// Mitsubishi GX Works2 project: ModbusTCP案例   PLC: L02

PROGRAM MAIN
0     END
END_PROGRAM

PROGRAM MB_TCP
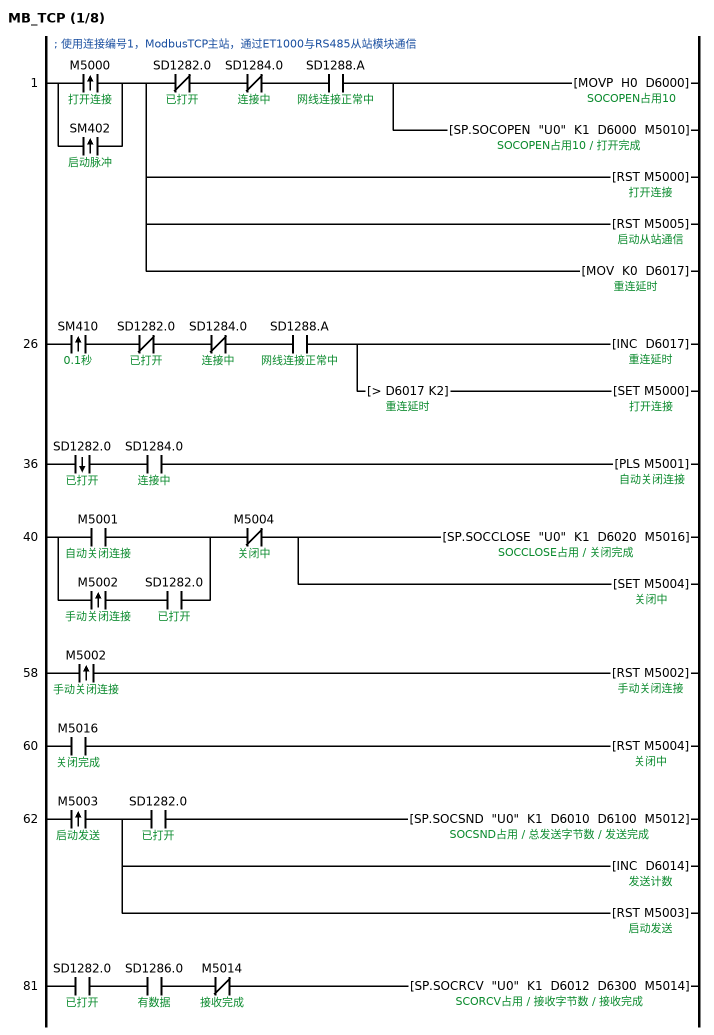
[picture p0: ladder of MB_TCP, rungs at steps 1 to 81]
; 使用连接编号1，ModbusTCP主站，通过ET1000与RS485从站模块通信
1     LDP     M5000  ; 打开连接
      ORP     SM402  ; 启动脉冲
      MPS
      ANI     SD1282.0  ; 已打开
      ANI     SD1284.0  ; 连接中
      AND     SD1288.A  ; 网线连接正常中
      MOVP    H0 D6000  ; SOCOPEN占用10
      SP.SOCOPEN "U0" K1 D6000 M5010  ; 打开完成
      MPP
      RST     M5000  ; 打开连接
      RST     M5005  ; 启动从站通信
      MOV     K0 D6017  ; 重连延时
26    LDP     SM410  ; 0.1秒
      ANI     SD1282.0  ; 已打开
      ANI     SD1284.0  ; 连接中
      AND     SD1288.A  ; 网线连接正常中
      INC     D6017
      AND>    D6017 K2  ; 重连延时
      SET     M5000  ; 打开连接
36    LDF     SD1282.0  ; 已打开
      AND     SD1284.0  ; 连接中
      PLS     M5001  ; 自动关闭连接
40    LD      M5001  ; 自动关闭连接
      LDP     M5002  ; 手动关闭连接
      AND     SD1282.0  ; 已打开
      ORB
      ANI     M5004  ; 关闭中
      SP.SOCCLOSE "U0" K1 D6020 M5016  ; SOCCLOSE占用 / 关闭完成
      SET     M5004  ; 关闭中
58    LDP     M5002  ; 手动关闭连接
      RST     M5002  ; 手动关闭连接
60    LD      M5016  ; 关闭完成
      RST     M5004  ; 关闭中
62    LDP     M5003  ; 启动发送
      MPS
      AND     SD1282.0  ; 已打开
      SP.SOCSND "U0" K1 D6010 D6100 M5012  ; SOCSND占用 / 总发送字节数 / 发送完成
      MPP
      INC     D6014  ; 发送计数
      RST     M5003  ; 启动发送
81    LD      SD1282.0  ; 已打开
      AND     SD1286.0  ; 有数据
      ANI     M5014  ; 接收完成
      SP.SOCRCV "U0" K1 D6012 D6300 M5014  ; SCORCV占用 / 接收字节数
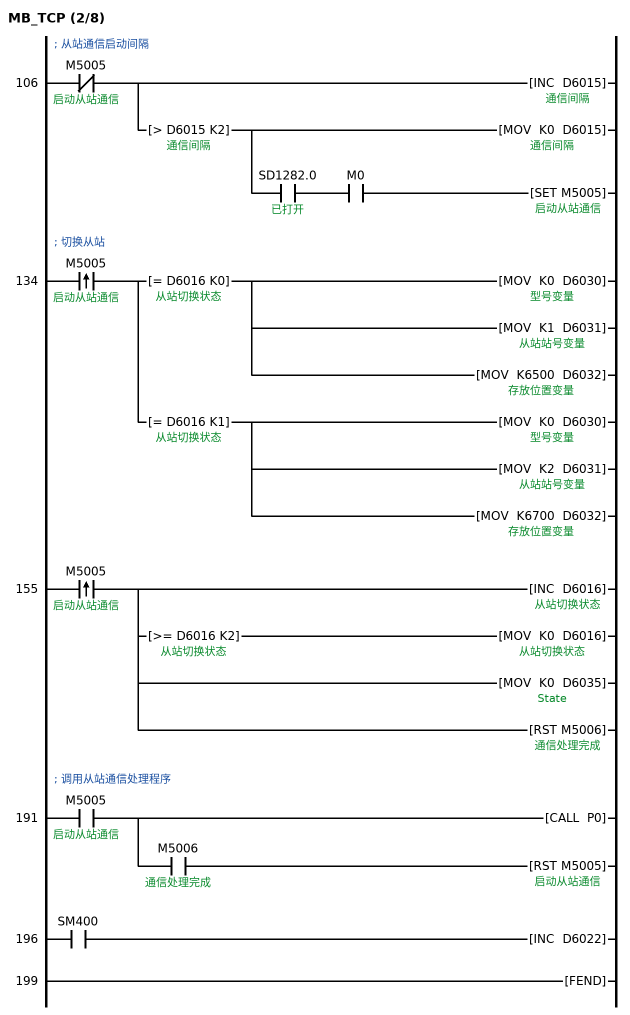
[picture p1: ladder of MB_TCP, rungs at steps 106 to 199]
; 从站通信启动间隔
106   LDI     M5005  ; 启动从站通信
      INC     D6015  ; 通信间隔
      AND>    D6015 K2  ; 通信间隔
      MOV     K0 D6015
      AND     SD1282.0  ; 已打开
      AND     M0
      SET     M5005  ; 启动从站通信
; 切换从站
134   LDP     M5005  ; 启动从站通信
      MPS
      AND=    D6016 K0  ; 从站切换状态
      MOV     K0 D6030  ; 型号变量
      MOV     K1 D6031  ; 从站站号变量
      MOV     K6500 D6032  ; 存放位置变量
      MPP
      AND=    D6016 K1  ; 从站切换状态
      MOV     K0 D6030
      MOV     K2 D6031
      MOV     K6700 D6032
155   LDP     M5005  ; 启动从站通信
      INC     D6016
      MPS
      AND>=   D6016 K2  ; 从站切换状态
      MOV     K0 D6016
      MPP
      MOV     K0 D6035  ; State
      RST     M5006  ; 通信处理完成
; 调用从站通信处理程序
191   LD      M5005  ; 启动从站通信
      CALL    P0
      AND     M5006  ; 通信处理完成
      RST     M5005  ; 启动从站通信
196   LD      SM400
      INC     D6022
199   FEND
; 对不同从站通信处理载程序
      P0
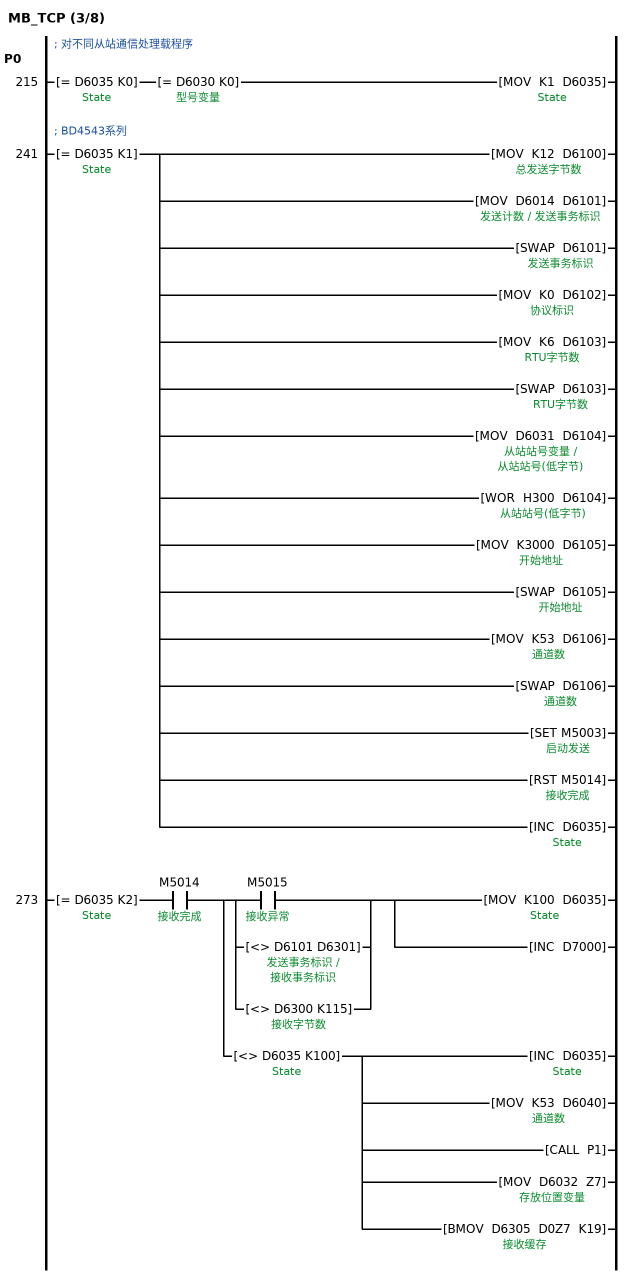
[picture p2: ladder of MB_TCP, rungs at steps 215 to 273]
215   LD=     D6035 K0  ; State
      AND=    D6030 K0  ; 型号变量
      MOV     K1 D6035
; BD4543系列
241   LD=     D6035 K1  ; State
      MOV     K12 D6100
      MOV     D6014 D6101  ; 发送事务标识
      SWAP    D6101
      MOV     K0 D6102  ; 协议标识
      MOV     K6 D6103  ; RTU字节数
      SWAP    D6103
      MOV     D6031 D6104  ; 从站站号(低字节)
      WOR     H300 D6104
      MOV     K3000 D6105  ; 开始地址
      SWAP    D6105
      MOV     K53 D6106  ; 通道数
      SWAP    D6106
      SET     M5003  ; 启动发送
      RST     M5014  ; 接收完成
      INC     D6035
273   LD=     D6035 K2  ; State
      AND     M5014  ; 接收完成
      MPS
      LD      M5015  ; 接收异常
      OR<>    D6101 D6301  ; 发送事务标识 / 接收事务标识
      OR<>    D6300 K115  ; 接收字节数
      ANB
      MOV     K100 D6035
      INC     D7000
      MPP
      AND<>   D6035 K100  ; State
      INC     D6035
      MOV     K53 D6040  ; 通道数
      CALL    P1
      MOV     D6032 Z7
      BMOV    D6305 D0Z7 K19  ; 接收缓存
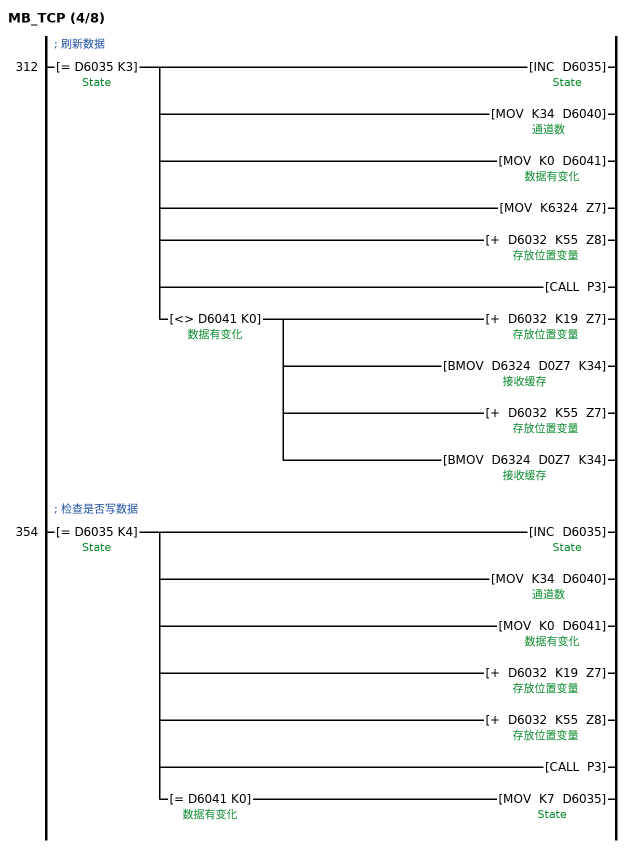
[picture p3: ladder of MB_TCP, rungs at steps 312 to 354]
; 刷新数据
312   LD=     D6035 K3  ; State
      INC     D6035
      MOV     K34 D6040
      MOV     K0 D6041  ; 数据有变化
      MOV     K6324 Z7
      +       D6032 K55 Z8
      CALL    P3
      AND<>   D6041 K0  ; 数据有变化
      +       D6032 K19 Z7
      BMOV    D6324 D0Z7 K34  ; 接收缓存
      +       D6032 K55 Z7
      BMOV    D6324 D0Z7 K34
; 检查是否写数据
354   LD=     D6035 K4  ; State
      INC     D6035
      MOV     K34 D6040
      MOV     K0 D6041
      +       D6032 K19 Z7
      +       D6032 K55 Z8
      CALL    P3
      AND=    D6041 K0  ; 数据有变化
      MOV     K7 D6035
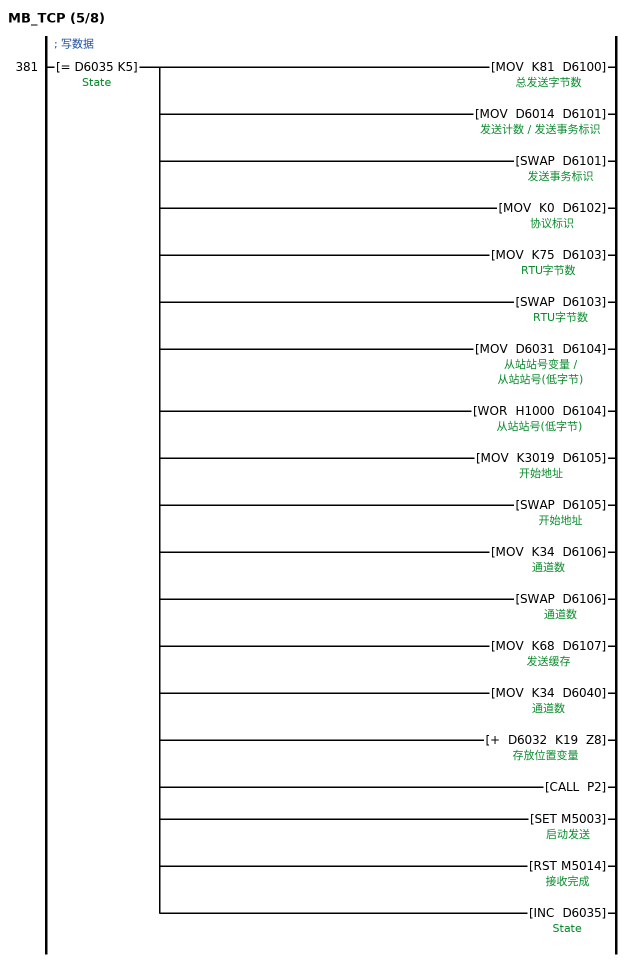
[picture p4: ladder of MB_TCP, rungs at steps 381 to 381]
; 写数据
381   LD=     D6035 K5  ; State
      MOV     K81 D6100
      MOV     D6014 D6101
      SWAP    D6101
      MOV     K0 D6102
      MOV     K75 D6103
      SWAP    D6103
      MOV     D6031 D6104
      WOR     H1000 D6104
      MOV     K3019 D6105
      SWAP    D6105
      MOV     K34 D6106
      SWAP    D6106
      MOV     K68 D6107  ; 发送缓存
      MOV     K34 D6040
      +       D6032 K19 Z8
      CALL    P2
      SET     M5003  ; 启动发送
      RST     M5014  ; 接收完成
      INC     D6035
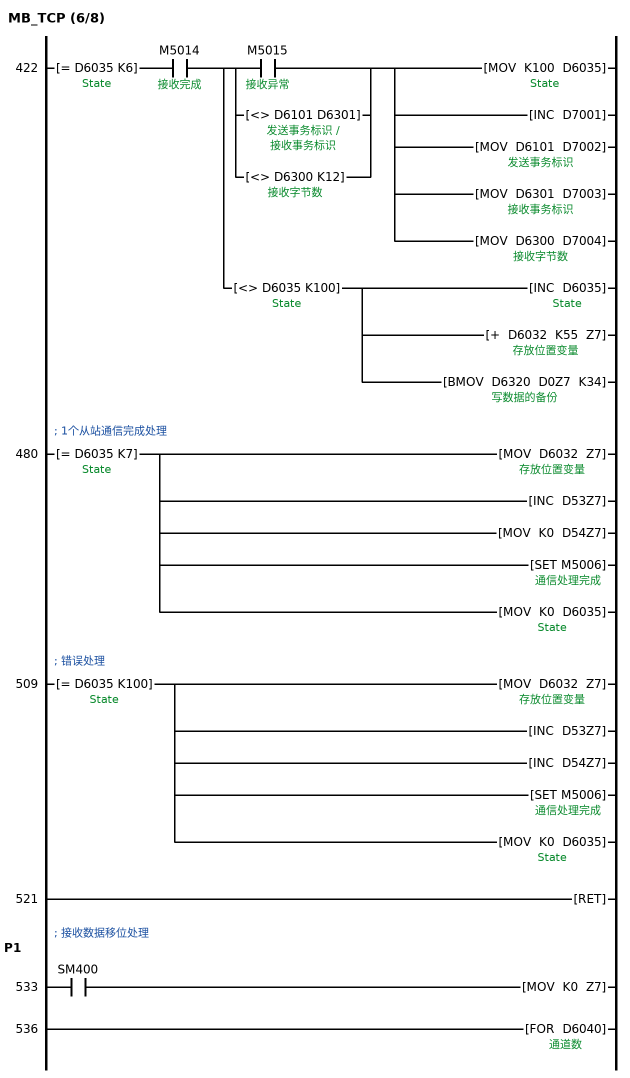
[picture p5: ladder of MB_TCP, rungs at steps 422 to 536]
422   LD=     D6035 K6  ; State
      AND     M5014  ; 接收完成
      MPS
      LD      M5015  ; 接收异常
      OR<>    D6101 D6301  ; 发送事务标识 / 接收事务标识
      OR<>    D6300 K12  ; 接收字节数
      ANB
      MOV     K100 D6035
      INC     D7001
      MOV     D6101 D7002
      MOV     D6301 D7003
      MOV     D6300 D7004
      MPP
      AND<>   D6035 K100  ; State
      INC     D6035
      +       D6032 K55 Z7
      BMOV    D6320 D0Z7 K34  ; 写数据的备份
; 1个从站通信完成处理
480   LD=     D6035 K7  ; State
      MOV     D6032 Z7
      INC     D53Z7
      MOV     K0 D54Z7
      SET     M5006  ; 通信处理完成
      MOV     K0 D6035
; 错误处理
509   LD=     D6035 K100  ; State
      MOV     D6032 Z7
      INC     D53Z7
      INC     D54Z7
      SET     M5006  ; 通信处理完成
      MOV     K0 D6035
521   RET
; 接收数据移位处理
      P1
533   LD      SM400
      MOV     K0 Z7
536   FOR     D6040
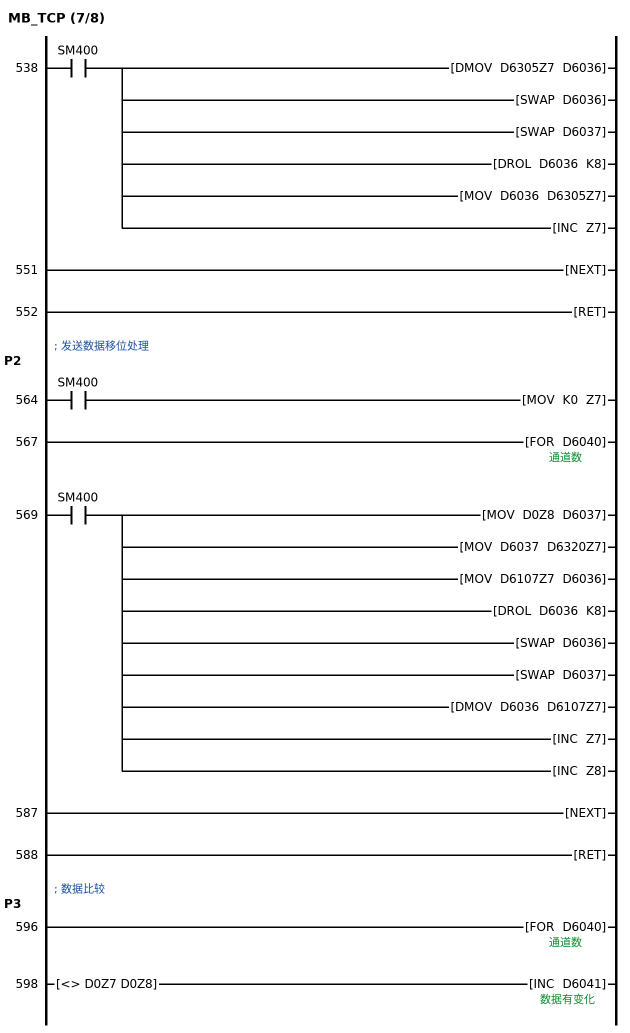
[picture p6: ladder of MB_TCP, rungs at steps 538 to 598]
538   LD      SM400
      DMOV    D6305Z7 D6036
      SWAP    D6036
      SWAP    D6037
      DROL    D6036 K8
      MOV     D6036 D6305Z7
      INC     Z7
551   NEXT
552   RET
; 发送数据移位处理
      P2
564   LD      SM400
      MOV     K0 Z7
567   FOR     D6040
569   LD      SM400
      MOV     D0Z8 D6037
      MOV     D6037 D6320Z7
      MOV     D6107Z7 D6036
      DROL    D6036 K8
      SWAP    D6036
      SWAP    D6037
      DMOV    D6036 D6107Z7
      INC     Z7
      INC     Z8
587   NEXT
588   RET
; 数据比较
      P3
596   FOR     D6040
598   LD<>    D0Z7 D0Z8
      INC     D6041
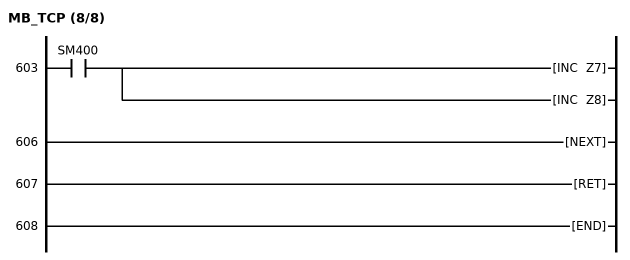
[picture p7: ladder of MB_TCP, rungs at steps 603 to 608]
603   LD      SM400
      INC     Z7
      INC     Z8
606   NEXT
607   RET
608   END
END_PROGRAM

// device comments not shown above
M5011  ; 打开异常
M5013  ; 发送异常
D53  ; 通信计数
D54  ; 故障计数
D6011  ; SOCSND占用
D6013  ; SCORCV占用
D6021  ; 关闭状态
